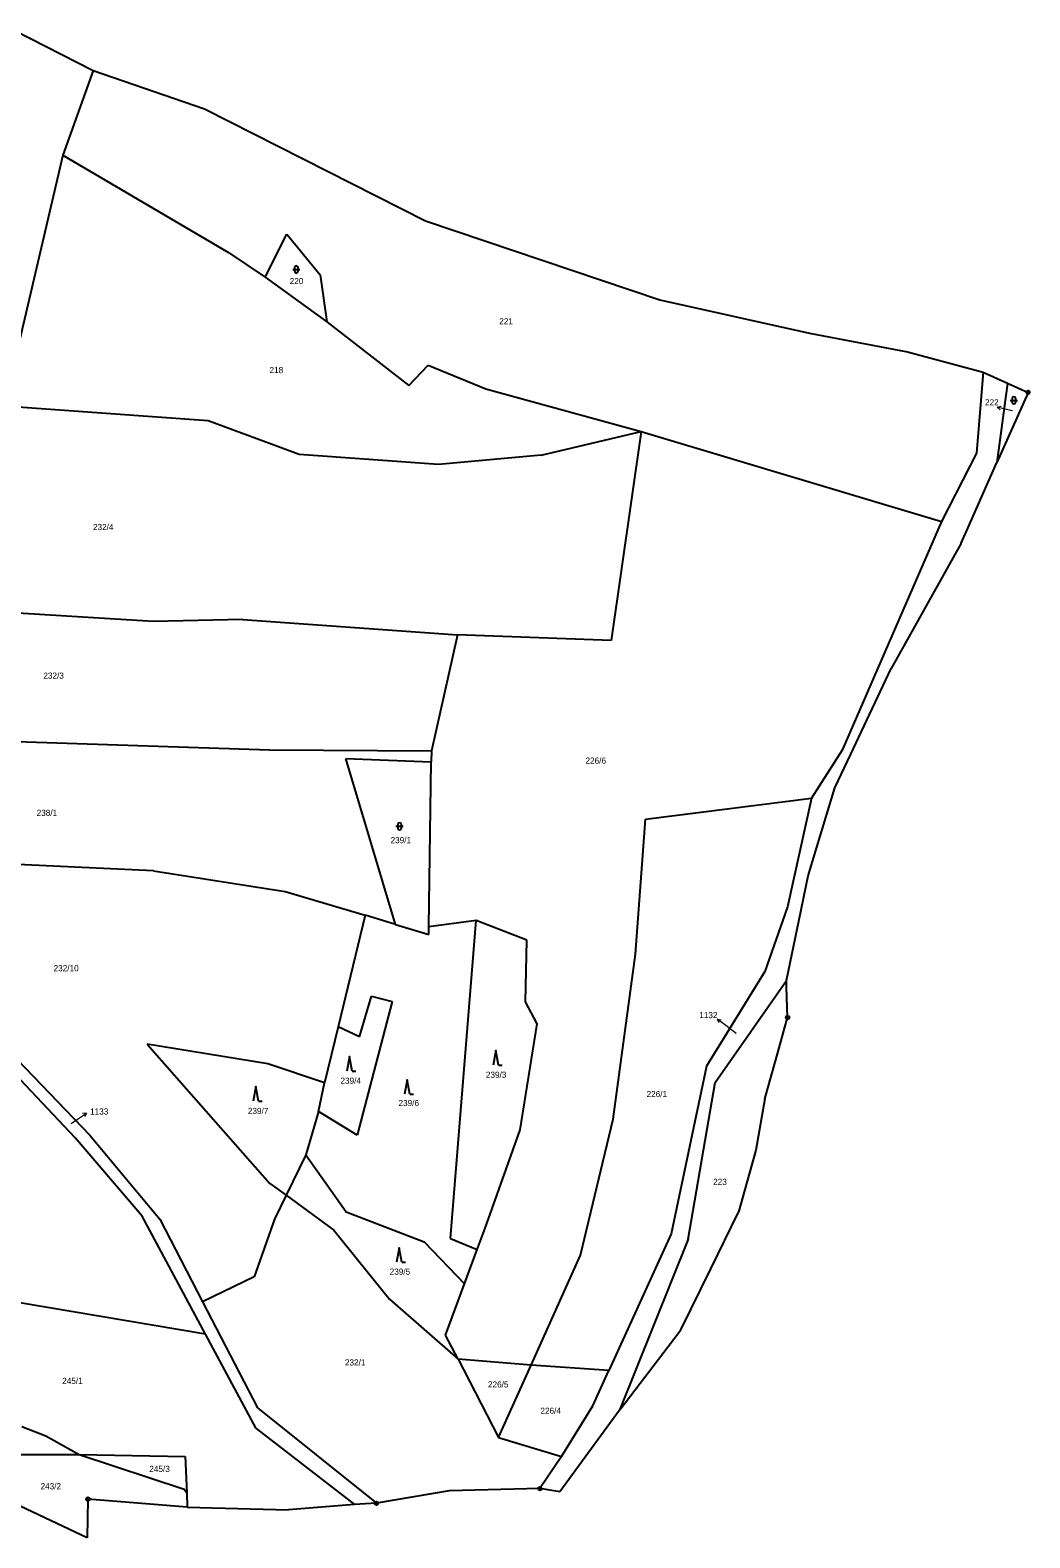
# Model space of a CAD drawing. Extents: x -765428 to -762163, y -1107632 to -1104975.
# Drawn here: x -762440.6 to -762163.3, y -1106346.5 to -1105928.5 of the extents above; entities that cross this region are included whole.
import ezdxf
from ezdxf.enums import TextEntityAlignment as Align

# ---------------------------------------------------------------- set-up
doc = ezdxf.new("R2010")
doc.units = 0
doc.header["$LTSCALE"] = 0.68
for name, color, linetype, lineweight in [('1', 7, 'Continuous', 25), ('3', 7, 'Continuous', 25), ('7', 7, 'Continuous', 13), ('8', 7, 'Continuous', 25)]:
    doc.layers.add(name, color=color, linetype=linetype, lineweight=lineweight)
doc.layers.add('2', color=7, linetype='Continuous')

msp = doc.modelspace()

# ---------------------------------------------------------------- linework, layer by layer
at = {"layer": '1'}
for p, q in [((-762445, -1105928.47), (-762423.13, -1105939.64)), ((-762423.13, -1105939.64), (-762431.5, -1105963.09)), ((-762423.13, -1105939.64), (-762392.17, -1105950.26)), ((-762392.17, -1105950.26), (-762330.9, -1105981.37)), ((-762431.5, -1105963.09), (-762447.76, -1106032.7)), ((-762431.5, -1105963.09), (-762385.52, -1105990.12)), ((-762330.9, -1105981.37), (-762265.89, -1106003.28)), ((-762375.39, -1105996.92), (-762369.37, -1105985.03)), ((-762369.37, -1105985.03), (-762360.15, -1105996.32)), ((-762385.52, -1105990.12), (-762375.39, -1105996.92)), ((-762375.39, -1105996.92), (-762358.31, -1106009.32)), ((-762360.15, -1105996.32), (-762358.31, -1106009.32)), ((-762265.89, -1106003.28), (-762224.41, -1106012.51)), ((-762358.31, -1106009.32), (-762335.57, -1106026.97)), ((-762224.41, -1106012.51), (-762197.19, -1106017.7)), ((-762197.19, -1106017.7), (-762176.21, -1106023.28)), ((-762335.57, -1106026.97), (-762330.16, -1106021.33)), ((-762330.16, -1106021.33), (-762314.21, -1106027.92)), ((-762176.21, -1106023.28), (-762178.12, -1106045.73)), ((-762314.21, -1106027.92), (-762271.06, -1106039.7)), ((-762169.52, -1106026.31), (-762172.46, -1106048.37)), ((-762163.8, -1106028.9), (-762172.46, -1106048.37)), ((-762391.21, -1106036.75), (-762447.76, -1106032.7)), ((-762365.96, -1106046.08), (-762391.21, -1106036.75)), ((-762298.8, -1106046.32), (-762271.06, -1106039.7)), ((-762271.06, -1106039.7), (-762279.4, -1106097.65)), ((-762271.06, -1106039.7), (-762187.85, -1106064.69)), ((-762327.27, -1106048.93), (-762365.96, -1106046.08)), ((-762178.12, -1106045.73), (-762187.85, -1106064.69)), ((-762298.8, -1106046.32), (-762327.27, -1106048.93)), ((-762180.44, -1106066.32), (-762172.46, -1106048.37)), ((-762187.85, -1106064.69), (-762215.34, -1106128.06)), ((-762182.38, -1106070.68), (-762180.44, -1106066.32)), ((-762182.38, -1106070.68), (-762201.73, -1106105.44)), ((-762406.49, -1106092.38), (-762498.78, -1106086.88)), ((-762381.54, -1106091.85), (-762406.49, -1106092.38)), ((-762381.54, -1106091.85), (-762322.04, -1106096.1)), ((-762322.04, -1106096.1), (-762329.25, -1106128.31)), ((-762279.4, -1106097.65), (-762322.04, -1106096.1)), ((-762212.94, -1106129.19), (-762201.73, -1106105.44)), ((-762465.16, -1106124.96), (-762374.2, -1106128.04)), ((-762374.2, -1106128.04), (-762329.25, -1106128.31)), ((-762329.25, -1106128.31), (-762329.33, -1106131.33)), ((-762215.34, -1106128.06), (-762223.89, -1106141.37)), ((-762217.37, -1106138.58), (-762212.94, -1106129.19)), ((-762352.97, -1106130.38), (-762329.33, -1106131.33)), ((-762339.28, -1106176.4), (-762352.97, -1106130.38)), ((-762329.97, -1106177.03), (-762329.33, -1106131.33)), ((-762269.9, -1106147.2), (-762223.89, -1106141.37)), ((-762223.89, -1106141.37), (-762230.5, -1106171.54)), ((-762222.34, -1106155.01), (-762217.37, -1106138.58)), ((-762272.63, -1106184.69), (-762269.9, -1106147.2)), ((-762406.4, -1106161.56), (-762466.9, -1106158.74)), ((-762224.74, -1106162.95), (-762222.34, -1106155.01)), ((-762406.4, -1106161.56), (-762369.85, -1106167.28)), ((-762227.28, -1106175.06), (-762224.74, -1106162.95)), ((-762369.85, -1106167.28), (-762347.66, -1106173.83)), ((-762347.66, -1106173.83), (-762355.14, -1106204.83)), ((-762339.28, -1106176.4), (-762347.66, -1106173.83)), ((-762316.82, -1106175.28), (-762329.97, -1106177.03)), ((-762323.97, -1106263.47), (-762316.82, -1106175.28)), ((-762302.79, -1106180.73), (-762316.82, -1106175.28)), ((-762230.5, -1106171.54), (-762236.76, -1106189.43)), ((-762230.83, -1106192), (-762227.28, -1106175.06)), ((-762339.28, -1106176.4), (-762330, -1106179.17)), ((-762330, -1106179.17), (-762329.97, -1106177.03)), ((-762303.14, -1106197.84), (-762302.79, -1106180.73)), ((-762278.84, -1106230.44), (-762272.63, -1106184.69)), ((-762236.76, -1106189.43), (-762252.98, -1106215.68)), ((-762250.57, -1106220.22), (-762230.83, -1106192)), ((-762230.77, -1106193.79), (-762230.83, -1106192)), ((-762349.19, -1106207.61), (-762345.87, -1106196.28)), ((-762345.87, -1106196.28), (-762340.14, -1106197.8)), ((-762230.5, -1106202.24), (-762230.77, -1106193.79)), ((-762340.14, -1106197.8), (-762349.88, -1106234.87)), ((-762299.91, -1106203.95), (-762303.14, -1106197.84)), ((-762355.14, -1106204.83), (-762358.89, -1106220.35)), ((-762349.19, -1106207.61), (-762355.14, -1106204.83)), ((-762304.65, -1106233.35), (-762299.91, -1106203.95)), ((-762233.15, -1106211.68), (-762230.5, -1106202.24)), ((-762374.65, -1106215.1), (-762408.08, -1106209.6)), ((-762408.08, -1106209.6), (-762374.07, -1106248.24)), ((-762236.83, -1106224.78), (-762233.15, -1106211.68)), ((-762428.1, -1106235.54), (-762446.28, -1106216.25)), ((-762444.17, -1106213.85), (-762423.97, -1106234.8)), ((-762358.89, -1106220.35), (-762374.65, -1106215.1)), ((-762252.98, -1106215.68), (-762262.77, -1106262.22)), ((-762360.62, -1106228.3), (-762358.89, -1106220.35)), ((-762258.11, -1106263.65), (-762250.57, -1106220.22)), ((-762236.83, -1106224.78), (-762239.3, -1106239.02)), ((-762360.62, -1106228.3), (-762364.1, -1106240.31)), ((-762349.88, -1106234.87), (-762360.62, -1106228.3)), ((-762314.36, -1106260.58), (-762304.65, -1106233.35)), ((-762287.9, -1106268.13), (-762278.84, -1106230.44)), ((-762409.51, -1106257.27), (-762428.1, -1106235.54)), ((-762423.97, -1106234.8), (-762404.63, -1106258.12)), ((-762364.1, -1106240.31), (-762369.58, -1106251.51)), ((-762364.1, -1106240.31), (-762352.96, -1106256.06)), ((-762239.3, -1106239.02), (-762244.08, -1106256.14)), ((-762374.07, -1106248.24), (-762369.58, -1106251.51)), ((-762369.58, -1106251.51), (-762372.82, -1106258.13)), ((-762369.58, -1106251.51), (-762356.35, -1106261.15)), ((-762391.9, -1106290.04), (-762409.51, -1106257.27)), ((-762404.63, -1106258.12), (-762392.76, -1106281)), ((-762372.82, -1106258.13), (-762378.44, -1106274.12)), ((-762352.96, -1106256.06), (-762331.29, -1106264.39)), ((-762251.78, -1106271.88), (-762244.08, -1106256.14)), ((-762356.35, -1106261.15), (-762340.9, -1106280.31)), ((-762316.58, -1106266.52), (-762314.36, -1106260.58)), ((-762262.77, -1106262.22), (-762280.09, -1106300.08)), ((-762331.29, -1106264.39), (-762320.12, -1106276.02)), ((-762323.97, -1106263.47), (-762316.58, -1106266.52)), ((-762320.12, -1106276.02), (-762316.58, -1106266.52)), ((-762258.11, -1106263.65), (-762277.08, -1106311.05)), ((-762301.62, -1106298.59), (-762287.9, -1106268.13)), ((-762378.44, -1106274.12), (-762392.76, -1106281)), ((-762260.08, -1106288.82), (-762251.78, -1106271.88)), ((-762325.35, -1106290.26), (-762320.12, -1106276.02)), ((-762391.9, -1106290.04), (-762443.44, -1106281.29)), ((-762392.76, -1106281), (-762377.49, -1106310.4)), ((-762340.9, -1106280.31), (-762321.9, -1106296.97)), ((-762377.9, -1106316.16), (-762391.9, -1106290.04)), ((-762321.9, -1106296.97), (-762325.35, -1106290.26)), ((-762263.58, -1106293.39), (-762260.08, -1106288.82)), ((-762276.78, -1106310.64), (-762263.58, -1106293.39)), ((-762321.9, -1106296.97), (-762310.65, -1106318.63)), ((-762301.62, -1106298.59), (-762321.9, -1106296.97)), ((-762310.65, -1106318.63), (-762301.62, -1106298.59)), ((-762280.09, -1106300.08), (-762301.62, -1106298.59)), ((-762284.52, -1106309.89), (-762280.09, -1106300.08)), ((-762377.49, -1106310.4), (-762344.55, -1106336.9)), ((-762293.18, -1106323.95), (-762284.52, -1106309.89)), ((-762442.9, -1106315.59), (-762436.26, -1106318.17)), ((-762377.9, -1106316.16), (-762350.64, -1106337.27)), ((-762436.26, -1106318.17), (-762426.94, -1106323.33)), ((-762310.65, -1106318.63), (-762293.18, -1106323.95)), ((-762458.11, -1106323.37), (-762426.94, -1106323.33)), ((-762426.94, -1106323.33), (-762397.55, -1106323.91)), ((-762426.94, -1106323.33), (-762397.88, -1106333.02)), ((-762397.55, -1106323.91), (-762397.14, -1106334.02)), ((-762293.18, -1106323.95), (-762299.18, -1106332.83)), ((-762424.77, -1106346.48), (-762467.35, -1106326.43)), ((-762397.88, -1106333.02), (-762397.14, -1106334.02)), ((-762397.14, -1106334.02), (-762396.98, -1106337.96)), ((-762324.32, -1106333.4), (-762344.55, -1106336.9)), ((-762299.18, -1106332.83), (-762324.32, -1106333.4)), ((-762293.67, -1106333.73), (-762299.18, -1106332.83)), ((-762424.55, -1106335.74), (-762424.77, -1106346.48)), ((-762396.98, -1106337.96), (-762424.55, -1106335.74)), ((-762396.98, -1106337.96), (-762368.96, -1106338.7)), ((-762350.64, -1106337.27), (-762368.96, -1106338.7)), ((-762344.55, -1106336.9), (-762350.64, -1106337.27))]:
    msp.add_line(p, q, dxfattribs=at)
for points in [[(-762176.21, -1106023.28), (-762169.52, -1106026.31), (-762163.8, -1106028.9)], [(-762276.78, -1106310.64), (-762277.08, -1106311.05), (-762293.67, -1106333.73)]]:
    msp.add_lwpolyline(points, dxfattribs=at)
at = {"layer": '3'}
for p, q in [((-762367.731, -1105994.811), (-762365.729, -1105994.811)), ((-762367.231, -1105994.311), (-762367.231, -1105995.312)), ((-762366.229, -1105995.312), (-762366.229, -1105994.311)), ((-762168.731, -1106031.111), (-762166.729, -1106031.111)), ((-762168.231, -1106030.611), (-762168.231, -1106031.612)), ((-762167.229, -1106031.612), (-762167.229, -1106030.611)), ((-762339.101, -1106149.201), (-762337.099, -1106149.201)), ((-762338.601, -1106148.701), (-762338.601, -1106149.702)), ((-762337.599, -1106149.702), (-762337.599, -1106148.701)), ((-762351.26, -1106217.05), (-762350.264, -1106217.05)), ((-762310.67, -1106215.39), (-762309.674, -1106215.39)), ((-762377.19, -1106225.38), (-762376.194, -1106225.38)), ((-762335.26, -1106223.48), (-762334.264, -1106223.48)), ((-762337.47, -1106270.04), (-762336.474, -1106270.04))]:
    msp.add_line(p, q, dxfattribs=at)
for points in [[(-762351.26, -1106217.05), (-762352.01, -1106213.05), (-762352.76, -1106217.05)], [(-762310.67, -1106215.39), (-762311.42, -1106211.39), (-762312.17, -1106215.39)], [(-762377.19, -1106225.38), (-762377.94, -1106221.38), (-762378.69, -1106225.38)], [(-762335.26, -1106223.48), (-762336.01, -1106219.48), (-762336.76, -1106223.48)], [(-762337.47, -1106270.04), (-762338.22, -1106266.04), (-762338.97, -1106270.04)]]:
    msp.add_lwpolyline(points, dxfattribs=at)
for centre, start, end in [((-762366.73, -1105994.3109), 0, 180), ((-762366.73, -1105995.3109), 180, 359.98789), ((-762167.73, -1106030.6109), 0, 180), ((-762167.73, -1106031.6109), 180, 359.98789), ((-762338.1, -1106148.7009), 0, 180), ((-762338.1, -1106149.7009), 180, 359.98789)]:
    msp.add_arc(centre, 0.5, start, end, dxfattribs=at)
at = {"layer": '7'}
for p, q in [((-762172.362, -1106032.974), (-762171.511, -1106033.702)), ((-762250.017, -1106202.634), (-762249.518, -1106203.637)), ((-762424.942, -1106228.702), (-762426.052, -1106228.847))]:
    msp.add_line(p, q, dxfattribs=at)
for points in [[(-762168.07, -1106034.03), (-762169.45, -1106033.7), (-762172.362, -1106032.974), (-762171.269, -1106032.73)], [(-762244.73, -1106206.61), (-762247.62, -1106204.44), (-762250.017, -1106202.634), (-762248.916, -1106202.837)], [(-762429.21, -1106231.6), (-762427.43, -1106230.38), (-762424.942, -1106228.702), (-762425.492, -1106229.677)]]:
    msp.add_lwpolyline(points, dxfattribs=at)
at = {"layer": '8'}
for centre, radius in [((-762163.8, -1106028.8999), 0.5), ((-762163.8, -1106028.8999), 0.0303), ((-762230.5, -1106202.2399), 0.5), ((-762230.5, -1106202.2399), 0.0303), ((-762299.18, -1106332.8299), 0.5), ((-762299.18, -1106332.8299), 0.0303), ((-762424.55, -1106335.7399), 0.5), ((-762424.55, -1106335.7399), 0.0303), ((-762344.55, -1106336.8999), 0.5), ((-762344.55, -1106336.8999), 0.0303)]:
    msp.add_circle(centre, radius, dxfattribs=at)

# ---------------------------------------------------------------- texts
at = {"layer": '2'}
for s, p in [('220', (-762368.58, -1105998.875)), ('221', (-762310.47, -1106010.025)), ('239/1', (-762340.61, -1106153.895)), ('1133', (-762423.95, -1106229.115)), ('223', (-762251.13, -1106248.615))]:
    msp.add_text(s, height=1.7, dxfattribs=at).set_placement(p)
for s, p in [('218', (-762372.289, -1106023.565)), ('232/4', (-762420.3, -1106067.075)), ('232/3', (-762434.06, -1106108.285)), ('226/6', (-762283.7, -1106131.835)), ('238/1', (-762435.92, -1106146.315)), ('232/10', (-762430.59, -1106189.385)), ('239/3', (-762311.33, -1106218.935)), ('239/4', (-762351.65, -1106220.575)), ('239/6', (-762335.56, -1106226.775)), ('226/1', (-762266.76, -1106224.285)), ('239/7', (-762377.34, -1106228.965)), ('239/5', (-762338.01, -1106273.515)), ('232/1', (-762350.42, -1106298.685)), ('245/1', (-762428.84, -1106303.815)), ('226/5', (-762310.75, -1106304.785)), ('226/4', (-762296.19, -1106312.095)), ('245/3', (-762404.68, -1106328.205)), ('243/2', (-762434.84, -1106333.005))]:
    msp.add_text(s, height=1.7, dxfattribs=at).set_placement(p, align=Align.CENTER)
for s, p in [('222', (-762171.949, -1106032.495)), ('1132', (-762249.94, -1106202.395))]:
    msp.add_text(s, height=1.7, dxfattribs=at).set_placement(p, align=Align.RIGHT)

doc.saveas('drawing.dxf')
